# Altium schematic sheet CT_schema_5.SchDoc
size 364 x 245 mm
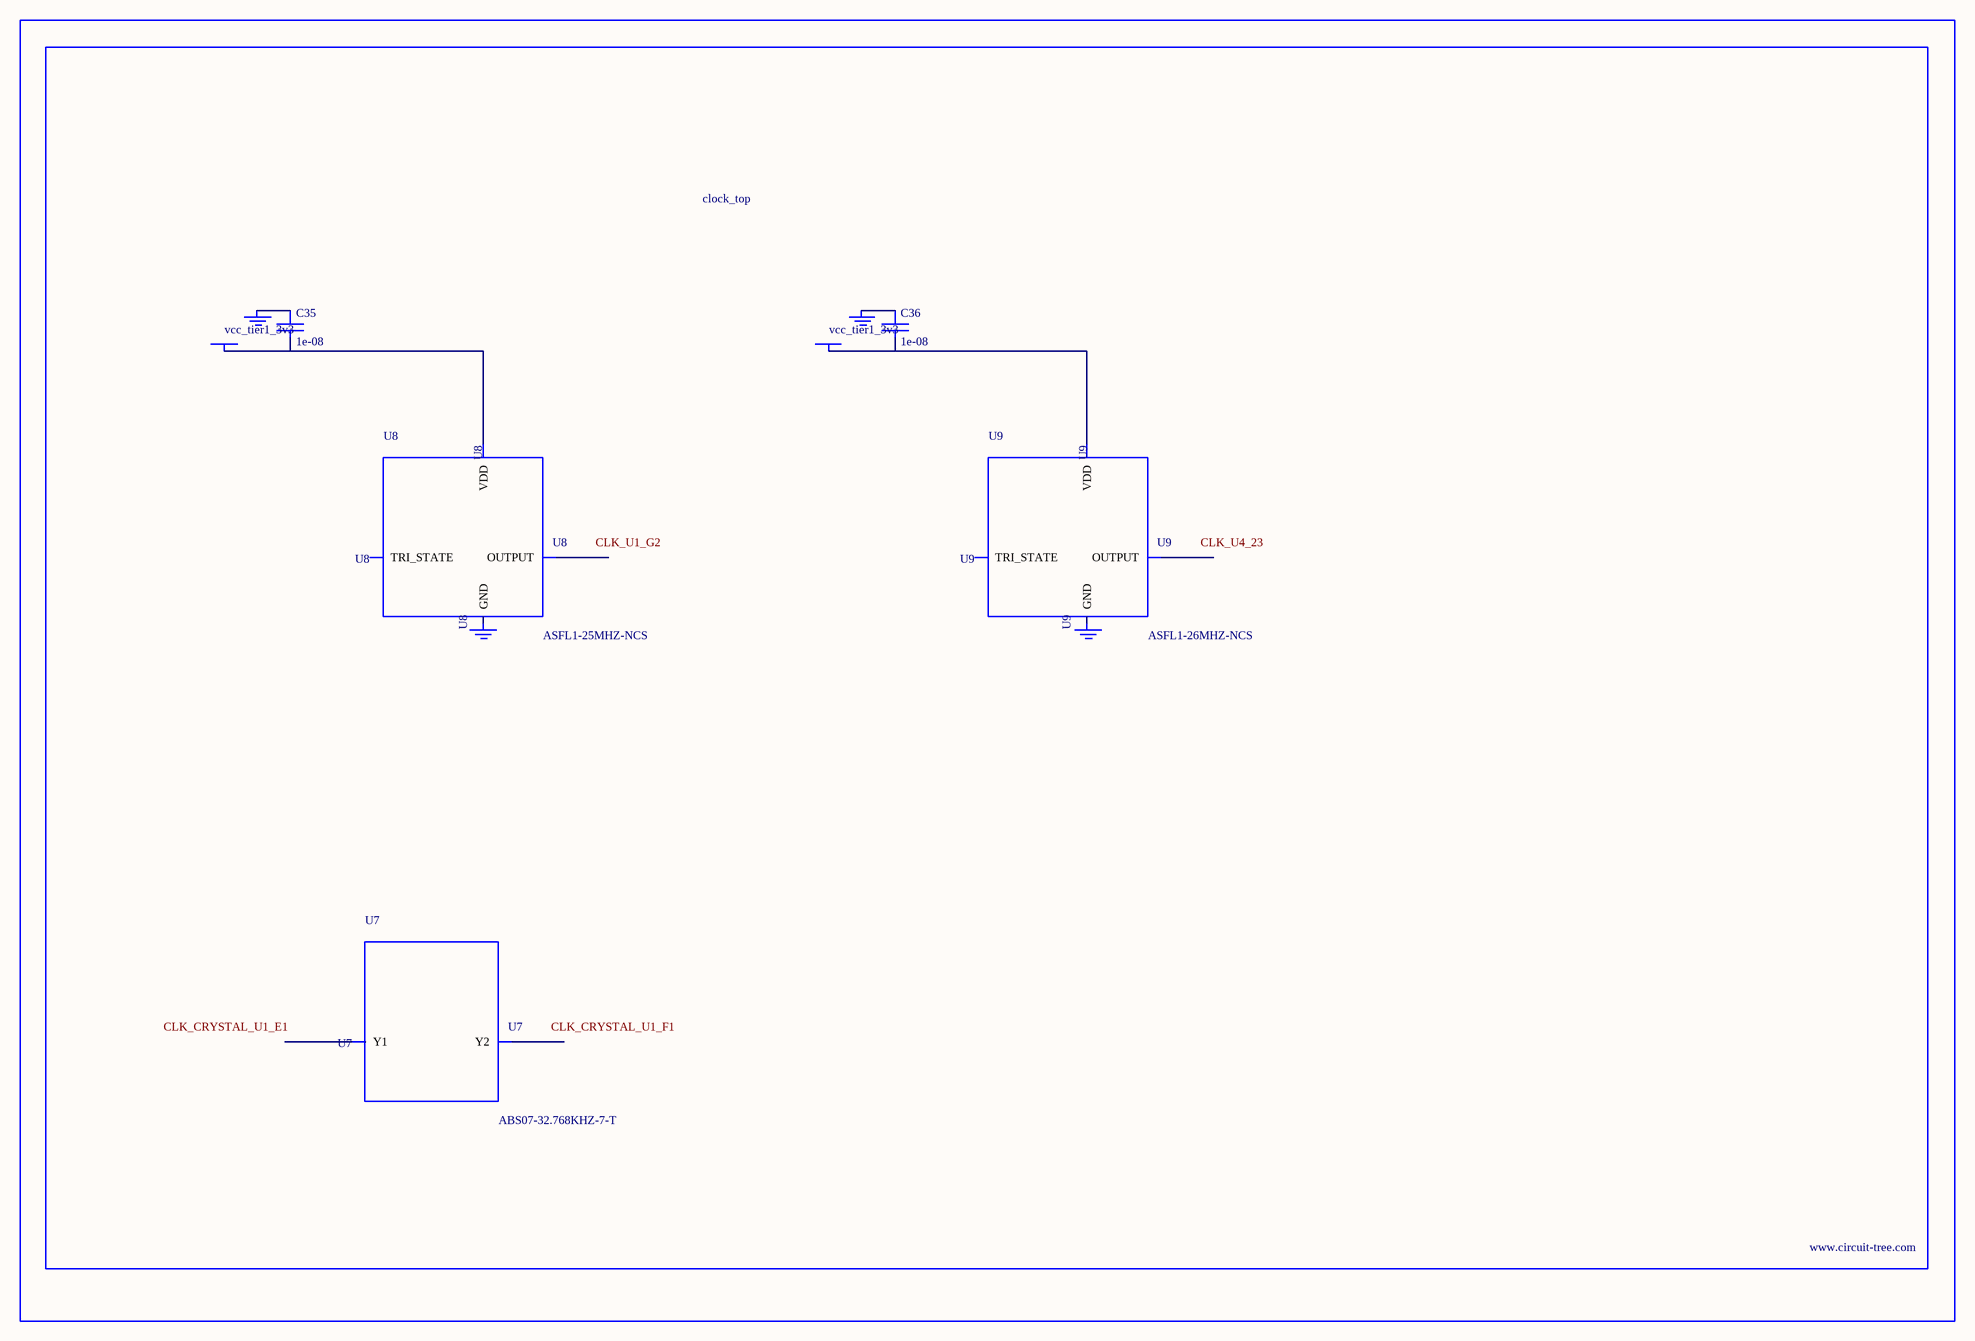
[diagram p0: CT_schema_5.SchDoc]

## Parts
BORDER4  (no value)
C35  1e-08  [C0402]
C36  1e-08  [C0402]
GND_INSTANCE_4_0  (no value)
GND_INSTANCE_4_1  (no value)
GND_INSTANCE_4_2  (no value)
GND_INSTANCE_4_3  (no value)
POWER_INSTANCE_4_0  vcc_tier1_3v3
POWER_INSTANCE_4_1  vcc_tier1_3v3
U7  ABS07-32.768KHZ-7-T  [ABS07-32.768KHZ-7-T]
U8  ASFL1-25MHZ-NCS  [ASFL1]
U9  ASFL1-26MHZ-NCS  [ASFL1]

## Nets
NetC35_1: C35.1 GND_INSTANCE_4_0.0(GND)
NetC35_2: C35.2 POWER_INSTANCE_4_0.0(PWR) U8.4(VDD)
NetC36_1: C36.1 GND_INSTANCE_4_2.0(GND)
NetC36_2: C36.2 POWER_INSTANCE_4_1.0(PWR) U9.4(VDD)

Not connected (* = marked no-connect by the designer): GND_INSTANCE_4_1 0(GND); GND_INSTANCE_4_3 0(GND); U7 1(Y1) 2(Y2); U8 1(TRI_STATE) 2(GND) 3(OUTPUT); U9 1(TRI_STATE) 2(GND) 3(OUTPUT)

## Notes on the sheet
- Labels drawn without touching a wire or pin: CLK_CRYSTAL_U1_E1, CLK_CRYSTAL_U1_F1, CLK_U1_G2, CLK_U4_23

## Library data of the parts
BORDER4 = BORDER_PAGE4
C35 C36 = C0402C103K3RAC
GND_INSTANCE_4_0-GND_INSTANCE_4_3 = GND
POWER_INSTANCE_4_0 POWER_INSTANCE_4_1 = PWR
